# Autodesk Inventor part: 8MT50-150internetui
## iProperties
Created: 2010-10
Part Number: 8MT50-150internetui
Document SubType Name: Modeling
Designer: Darius
Author: Darius
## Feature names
1. Base1
